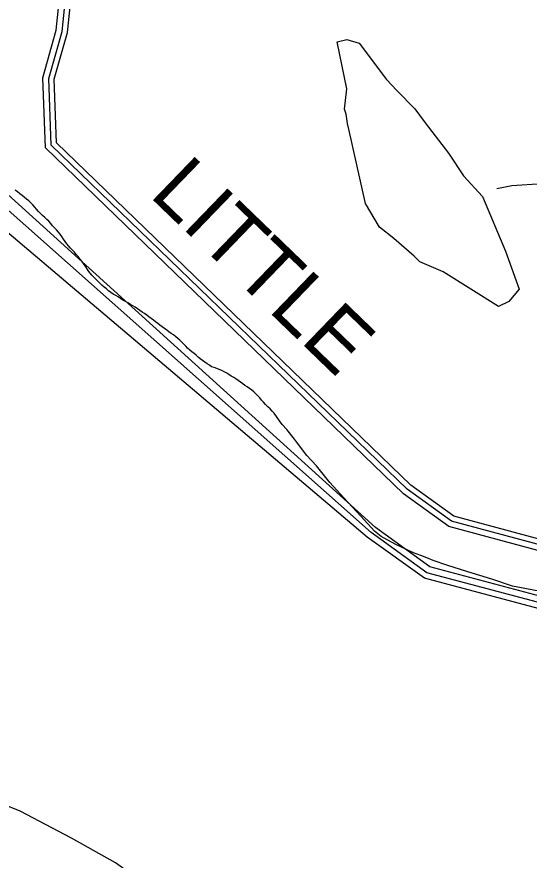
# Model space of a CAD drawing. Extents: x 2260773 to 2342389, y 552869 to 618546.
# Drawn here: x 2292755 to 2294183, y 608777 to 611126 of the extents above; entities that cross this region are included whole.
import ezdxf

# ---------------------------------------------------------------- set-up
doc = ezdxf.new("R2010")
doc.units = 0
for name, color, linetype in [('Exist Boundary Political City Limit New', 7, 'Continuous'), ('Exist Hydrographic Buffer Line', 7, 'Continuous'), ('Exist Hydrographic Misc Water Feature', 7, 'Continuous'), ('Exist Hydrographic River Shore', 7, 'Continuous'), ('Exist Hydrographic River Shore Label', 7, 'Continuous'), ('Exist Road Non-System Type 51', 7, 'Continuous'), ('Map Preparation Boundary City Limit Buffer Line', 7, 'Continuous')]:
    doc.layers.add(name, color=color, linetype=linetype)

msp = doc.modelspace()

# ---------------------------------------------------------------- linework, layer by layer
at = {"layer": 'Exist Boundary Political City Limit New'}
for points in [[(2293104.2, 610303.2), (2293097.8, 610307.7), (2293091.5, 610312.2), (2293085.2, 610316.7), (2293078.8, 610321.1), (2293072, 610324.9), (2293065, 610328.7), (2293058, 610332.6), (2293051, 610336.8), (2293044.2, 610341.1), (2293037.8, 610345.4), (2293030.8, 610349.5), (2293023.8, 610353.4), (2293017.2, 610357.9), (2293010.8, 610362.7), (2293004.8, 610367.8), (2292998.5, 610373.1), (2292992.5, 610378.4), (2292986.8, 610383.7), (2292980.8, 610389.3), (2292975.2, 610394.9), (2292969.5, 610400.8), (2292964.2, 610406.5), (2292960.8, 610410.5), (2292959, 610412.5), (2292954, 610418.8), (2292945.5, 610432.3), (2292941, 610438.8), (2292936.2, 610445.4), (2292931.2, 610451.7), (2292926.2, 610457.9), (2292921, 610463.9), (2292915.8, 610470), (2292910.5, 610475.9), (2292904.8, 610481.5), (2292899.8, 610487.5), (2292894.5, 610493.8), (2292890, 610500.2), (2292885.2, 610506.8), (2292880.8, 610513.4), (2292876.2, 610520.1), (2292871.5, 610526.2), (2292866, 610532.2), (2292860.5, 610538), (2292855, 610543.8), (2292850.2, 610550.2), (2292845, 610556.2), (2292839.2, 610561.6), (2292833.2, 610567.1), (2292827.2, 610572.5), (2292821.5, 610577.9), (2292815.8, 610583.8), (2292810.5, 610589.6), (2292805.2, 610595.6), (2292800, 610601.6), (2292794.2, 610607.2), (2292788.5, 610612.8), (2292782.5, 610617.9), (2292776.2, 610623.1), (2292770, 610628.1), (2292763.8, 610633), (2292757.2, 610637.9), (2292751, 610642.8)], [(2294209.8, 609525.8), (2294136.8, 609540.2), (2294078.5, 609559.3), (2294011.5, 609579.8), (2293953.2, 609598.6), (2293915, 609611.6), (2293897.8, 609619.3), (2293880.8, 609625.9), (2293860.8, 609632.8), (2293809.2, 609657.1), (2293770.5, 609678.2), (2293751.8, 609693.2), (2293713.8, 609735.4), (2293666.8, 609786.4), (2293627.8, 609829.2), (2293590, 609874.8), (2293563.8, 609904), (2293534.2, 609942), (2293529, 609949.1), (2293508, 609976.4), (2293494.8, 609990.4), (2293487.2, 610000.4), (2293472.8, 610021.8), (2293467.2, 610027.9), (2293461.2, 610034.1), (2293454.8, 610039.9), (2293448.5, 610045.7), (2293443, 610052.1), (2293437.5, 610058.5), (2293432, 610064.6), (2293426.8, 610070.4), (2293421.5, 610076.1), (2293416, 610081.7), (2293410, 610086.3), (2293403.8, 610090.8), (2293397.2, 610094.9), (2293391, 610098.9), (2293384.8, 610103.2), (2293378.2, 610107.8), (2293372.2, 610112.4), (2293366, 610117.1), (2293359.8, 610121.1), (2293353, 610125.1), (2293346.5, 610129.2), (2293340.2, 610133.3), (2293333.5, 610137), (2293326.8, 610140.4), (2293319.5, 610143.3), (2293312.5, 610146.1), (2293305.5, 610148.7), (2293298, 610151.2), (2293291.8, 610155.3), (2293285.5, 610159.6), (2293279, 610164.2), (2293273, 610168.6), (2293266.5, 610173.3), (2293260.8, 610177.9), (2293254.8, 610183.1), (2293249.2, 610188.2), (2293243, 610193.1), (2293237, 610197.6), (2293231.2, 610202.8), (2293225.8, 610208.2), (2293220.5, 610214.1), (2293215.2, 610219.9), (2293209.8, 610225), (2293203.8, 610230.2), (2293198, 610234.8), (2293191.5, 610239.6), (2293185.5, 610243.9), (2293179, 610248.4), (2293173, 610253), (2293166.8, 610257.6), (2293160.5, 610262.2), (2293154.2, 610266.8), (2293148, 610271.3), (2293141.8, 610275.9), (2293135.8, 610280.8), (2293129.8, 610285.7), (2293123.5, 610290.3), (2293117.2, 610294.8), (2293110.8, 610299.1), (2293104.2, 610303.2)]]:
    msp.add_lwpolyline(points, dxfattribs=at)
at = {"layer": 'Exist Hydrographic Buffer Line'}
for points in [[(2297540.2, 609590.8), (2297284.1, 609777.4), (2297000.4, 609824.5), (2296658.1, 609782.8), (2295759.9, 609428.4), (2295555, 609152.8), (2295524.9, 608980.3), (2295315, 609229.1), (2295191, 609280.4), (2295161.8, 609316), (2295176.5, 609563), (2294975.4, 609755.3), (2294519.1, 609626.5), (2294269.3, 609623.1), (2293959, 609705.9), (2293832.6, 609797.3), (2292835, 610760.6), (2292828, 610955.4), (2292865.2, 611088.2), (2292917.1, 611585.2)], [(2297549.9, 609604.1), (2297290.6, 609792.9), (2297000.7, 609841.1), (2296654, 609798.8), (2295749.5, 609442), (2295539.5, 609159.4), (2295514.8, 609017.8), (2295325, 609242.7), (2295201.1, 609294), (2295178.6, 609321.4), (2295193.3, 609569.6), (2294980, 609773.7), (2294516.7, 609642.9), (2294271.4, 609639.6), (2293966.2, 609721), (2293843.1, 609809.9), (2292851.1, 610767.8), (2292844.5, 610953.4), (2292881.4, 611085.1), (2292933.2, 611581.1)], [(2297477.3, 609486.3), (2297235.8, 609662.2), (2296997.7, 609701.7), (2296688.3, 609664), (2295836.8, 609328.1), (2295669.8, 609103.4), (2295638.4, 608923.6), (2295546.3, 608836.3), (2295467.9, 608859.4), (2295241.2, 609128.1), (2295116.4, 609179.7), (2295037.7, 609275.7), (2295051.8, 609514), (2294941.6, 609619.5), (2294536.8, 609505.2), (2294254.2, 609501.4), (2293906.1, 609594.3), (2293754.4, 609703.8), (2292680.6, 610675.6)], [(2297461.5, 609475.2), (2297228.5, 609644.9), (2296997.3, 609683.3), (2296692.8, 609646.2), (2295848.3, 609313), (2295687, 609096), (2295655.3, 608914.5), (2295551.3, 608815.8), (2295457.5, 608843.4), (2295230.1, 609112.9), (2295105.1, 609164.6), (2295019.1, 609269.7), (2295033.1, 609506.7), (2294936.5, 609599.1), (2294539.4, 609487), (2294251.9, 609483.1), (2293898.1, 609577.5), (2293742.6, 609689.8), (2292655.1, 610653.7)]]:
    msp.add_lwpolyline(points, dxfattribs=at)
at = {"layer": 'Exist Hydrographic Misc Water Feature'}
for points in [[(2293676.7, 610828.8), (2293672.6, 610854.6), (2293668.5, 610868.6), (2293675, 610925.4), (2293647.9, 611055.8), (2293675, 611062.6), (2293708.9, 611052.4), (2293785.1, 610950.8), (2293813.8, 610920.3), (2293864.6, 610869.5), (2293893.4, 610830.5), (2293957.7, 610745.8), (2294000.1, 610683.1), (2294052.5, 610625.5), (2294116.5, 610473.1), (2294155, 610367), (2294126.1, 610333.3), (2294097.2, 610318.8), (2293942.9, 610415.7), (2293878.1, 610442.9), (2293862.1, 610458.7), (2293805.7, 610508.1), (2293765.5, 610539.7), (2293726.8, 610605.6), (2293680.8, 610812.8), (2293676.7, 610828.8)], [(2293540.4, 608540.7), (2293496.1, 608540.4), (2293436.4, 608539.7), (2293356.2, 608571.2), (2293265.8, 608612), (2293157.5, 608679), (2293030.6, 608769.9), (2292907.8, 608838.7), (2292765.1, 608913.3), (2292667, 608952.4)]]:
    msp.add_lwpolyline(points, dxfattribs=at)
at = {"layer": 'Exist Hydrographic River Shore'}
for points in [[(2297558.8, 609616.3), (2297296.6, 609807.3), (2297001, 609856.4), (2296650.3, 609813.6), (2295739.9, 609454.5), (2295525.2, 609165.6), (2295505.4, 609052.3), (2295334.2, 609255.3), (2295210.4, 609306.5), (2295194.1, 609326.4), (2295208.8, 609575.7), (2294984.2, 609790.6), (2294514.5, 609658), (2294273.3, 609654.7), (2293972.8, 609734.9), (2293852.9, 609821.5), (2292866, 610774.5), (2292859.7, 610951.6), (2292896.3, 611082.3), (2292948, 611577.2)], [(2297448.9, 609463.7), (2297221.9, 609629), (2296996.9, 609666.4), (2296696.9, 609629.8), (2295858.9, 609299.2), (2295702.8, 609089.2), (2295670.9, 608906.2), (2295555.8, 608797.1), (2295448, 608828.8), (2295219.9, 609099), (2295094.9, 609150.7), (2295002, 609264.1), (2295015.9, 609499.9), (2294931.8, 609580.4), (2294541.8, 609470.3), (2294249.8, 609466.3), (2293890.8, 609562.1), (2293731.9, 609676.9), (2292611.3, 610624.5)]]:
    msp.add_lwpolyline(points, dxfattribs=at)
at = {"layer": 'Exist Road Non-System Type 51'}
msp.add_lwpolyline([(2295297.4, 610753.3), (2295239.3, 610719.3), (2295076.2, 610633.6), (2294943, 610568.5), (2294859.3, 610531.7), (2294797.4, 610517.1), (2294756.3, 610509.1), (2294692.5, 610507.5), (2294652, 610515.3), (2294605.3, 610529.3), (2294567.9, 610546.5), (2294518.1, 610588.5), (2294434, 610635.3), (2294370.1, 610655.5), (2294318.7, 610660.2), (2294219.1, 610660.2), (2294134.4, 610654.7), (2294092.7, 610646.4)], dxfattribs=at)
at = {"layer": 'Map Preparation Boundary City Limit Buffer Line'}
for points in [[(2293104.2, 610303.2), (2293097.8, 610307.7), (2293091.5, 610312.2), (2293085.2, 610316.7), (2293078.8, 610321.1), (2293072, 610324.9), (2293065, 610328.7), (2293058, 610332.6), (2293051, 610336.8), (2293044.2, 610341.1), (2293037.8, 610345.4), (2293030.8, 610349.5), (2293023.8, 610353.4), (2293017.2, 610357.9), (2293010.8, 610362.7), (2293004.8, 610367.8), (2292998.5, 610373.1), (2292992.5, 610378.4), (2292986.8, 610383.7), (2292980.8, 610389.3), (2292975.2, 610394.9), (2292969.5, 610400.8), (2292964.2, 610406.5), (2292960.8, 610410.5), (2292959, 610412.5), (2292954, 610418.8), (2292945.5, 610432.3), (2292941, 610438.8), (2292936.2, 610445.4), (2292931.2, 610451.7), (2292926.2, 610457.9), (2292921, 610463.9), (2292915.8, 610470), (2292910.5, 610475.9), (2292904.8, 610481.5), (2292899.8, 610487.5), (2292894.5, 610493.8), (2292890, 610500.2), (2292885.2, 610506.8), (2292880.8, 610513.4), (2292876.2, 610520.1), (2292871.5, 610526.2), (2292866, 610532.2), (2292860.5, 610538), (2292855, 610543.8), (2292850.2, 610550.2), (2292845, 610556.2), (2292839.2, 610561.6), (2292833.2, 610567.1), (2292827.2, 610572.5), (2292821.5, 610577.9), (2292815.8, 610583.8), (2292810.5, 610589.6), (2292805.2, 610595.6), (2292800, 610601.6), (2292794.2, 610607.2), (2292788.5, 610612.8), (2292782.5, 610617.9), (2292776.2, 610623.1), (2292770, 610628.1), (2292763.8, 610633), (2292757.2, 610637.9), (2292751, 610642.8)], [(2294209.8, 609525.8), (2294136.8, 609540.2), (2294078.5, 609559.3), (2294011.5, 609579.8), (2293953.2, 609598.6), (2293915, 609611.6), (2293897.8, 609619.3), (2293880.8, 609625.9), (2293860.8, 609632.8), (2293809.2, 609657.1), (2293770.5, 609678.2), (2293751.8, 609693.2), (2293713.8, 609735.4), (2293666.8, 609786.4), (2293627.8, 609829.2), (2293590, 609874.8), (2293563.8, 609904), (2293534.2, 609942), (2293529, 609949.1), (2293508, 609976.4), (2293494.8, 609990.4), (2293487.2, 610000.4), (2293472.8, 610021.8), (2293467.2, 610027.9), (2293461.2, 610034.1), (2293454.8, 610039.9), (2293448.5, 610045.7), (2293443, 610052.1), (2293437.5, 610058.5), (2293432, 610064.6), (2293426.8, 610070.4), (2293421.5, 610076.1), (2293416, 610081.7), (2293410, 610086.3), (2293403.8, 610090.8), (2293397.2, 610094.9), (2293391, 610098.9), (2293384.8, 610103.2), (2293378.2, 610107.8), (2293372.2, 610112.4), (2293366, 610117.1), (2293359.8, 610121.1), (2293353, 610125.1), (2293346.5, 610129.2), (2293340.2, 610133.3), (2293333.5, 610137), (2293326.8, 610140.4), (2293319.5, 610143.3), (2293312.5, 610146.1), (2293305.5, 610148.7), (2293298, 610151.2), (2293291.8, 610155.3), (2293285.5, 610159.6), (2293279, 610164.2), (2293273, 610168.6), (2293266.5, 610173.3), (2293260.8, 610177.9), (2293254.8, 610183.1), (2293249.2, 610188.2), (2293243, 610193.1), (2293237, 610197.6), (2293231.2, 610202.8), (2293225.8, 610208.2), (2293220.5, 610214.1), (2293215.2, 610219.9), (2293209.8, 610225), (2293203.8, 610230.2), (2293198, 610234.8), (2293191.5, 610239.6), (2293185.5, 610243.9), (2293179, 610248.4), (2293173, 610253), (2293166.8, 610257.6), (2293160.5, 610262.2), (2293154.2, 610266.8), (2293148, 610271.3), (2293141.8, 610275.9), (2293135.8, 610280.8), (2293129.8, 610285.7), (2293123.5, 610290.3), (2293117.2, 610294.8), (2293110.8, 610299.1), (2293104.2, 610303.2)]]:
    msp.add_lwpolyline(points, dxfattribs=at)

# ---------------------------------------------------------------- texts
at = {"layer": 'Exist Hydrographic River Shore Label'}
msp.add_text('LITTLE', height=167.32, rotation=316.0007, dxfattribs=at).set_placement((2293121.6, 610628))

doc.saveas('drawing.dxf')
